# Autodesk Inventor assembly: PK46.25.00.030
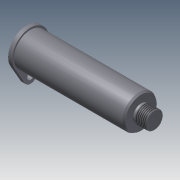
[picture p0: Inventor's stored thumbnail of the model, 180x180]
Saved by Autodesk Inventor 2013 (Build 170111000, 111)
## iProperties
Created: 2005-05
Part Number: PK46.25.00.030
Document SubType Name: Assembly
Designer: PVitaliy
Manufacturer: Standard
Standards Organization: Custom
Author: PVitaliy
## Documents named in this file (3)
- D:\FrontLoaderVault\Data\Assy, Chassis, Front\PK46.25.00.030.iam
- D:\FrontLoaderVault\Data\Assy, Chassis, Front\PK46.25.00.004.ipt
- D:\FrontLoaderVault\Data\Assy, Chassis, Front\PK46.25.00.002.ipt
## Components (2 placed, 2 different names)
1. PK46.25.00.004:1 — Insert:1
2. PK46.25.00.002:1 — Insert:1, Mate:1
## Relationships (2: Insert 1, Mate 1)
- Insert:1: PK46.25.00.004:1 ↔ PK46.25.00.002:1
- Mate:1: PK46.25.00.002:1
